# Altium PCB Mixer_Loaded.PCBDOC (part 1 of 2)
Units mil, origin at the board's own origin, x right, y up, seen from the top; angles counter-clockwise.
Board outline 16350 x 11350 mil, 2 copper layers (Top Layer, Bottom Layer); 554 components, 386 nets, 1551 pads, 0 vias.
Unrouted connection lines stored in the file: 1047.
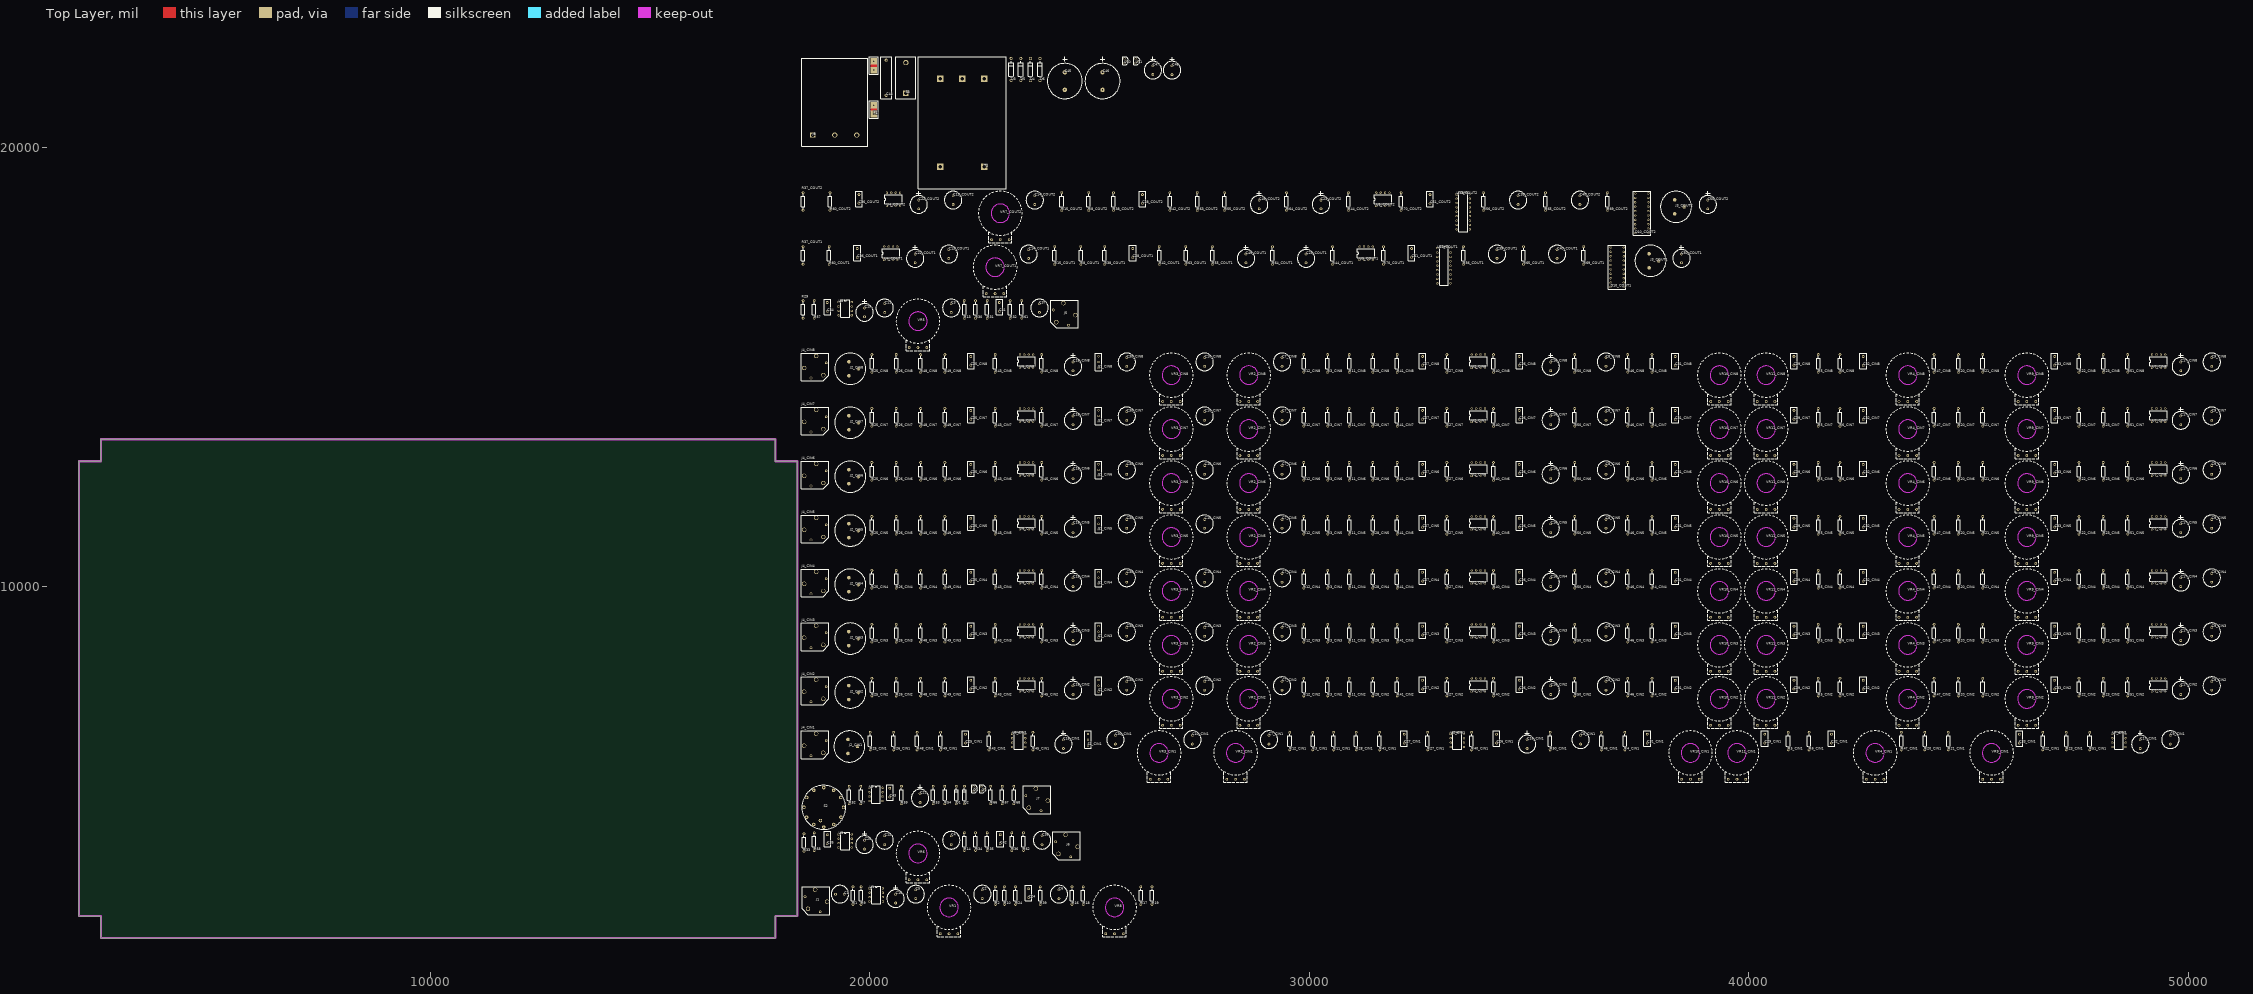
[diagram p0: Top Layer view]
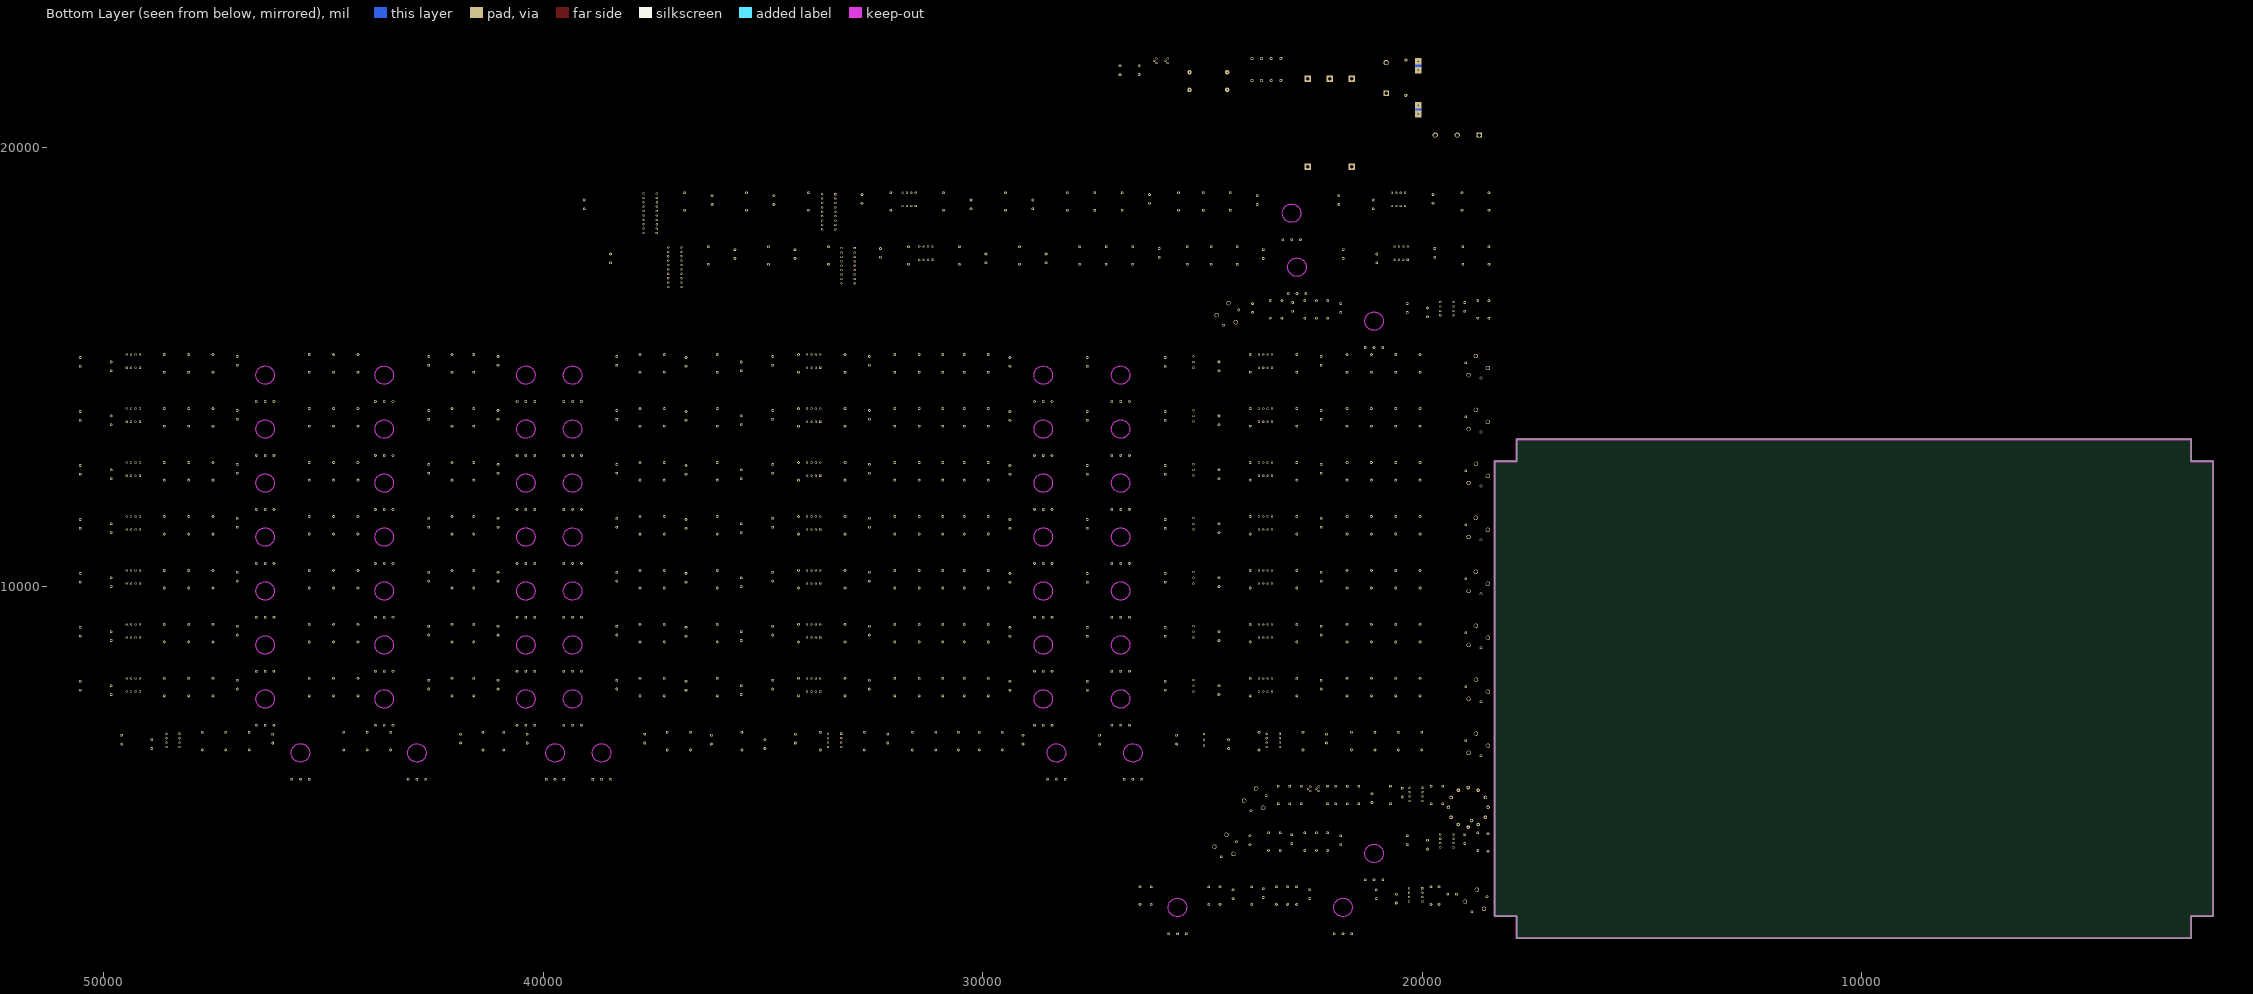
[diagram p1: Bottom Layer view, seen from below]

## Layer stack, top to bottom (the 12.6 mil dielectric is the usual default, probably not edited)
Top Layer: signal copper 1.4
Dielectric: dielectric 12.6, FR-4, Dk 4.8
Bottom Layer: signal copper 1.4

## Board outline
2500,2000 17850,2000 17850,2500 18350,2500 18350,12850 17850,12850 17850,13350 2500,13350 2500,12850 2000,12850 2000,2500 2500,2500

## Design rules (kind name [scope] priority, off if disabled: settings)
Clearance [All] p1: gap=10
FabricationTestPointUsage TestPointUsage [All] p1: valid=0 allowmultiple=FALSE
FabricationTestpoint Testpoint [All] p1: side=3 testpointundercomponent=TRUE minsize=40 maxsize=100 preferedsize=60 minholesize=0 maxholesize=40 preferedholesize=32 testpointgrid=1 allowsidetop=TRUE allowsidebottom=TRUE usegrid=TRUE gridtolerance=0.01
PolygonConnect [All] p1: connectstyle=Relief reliefconductorwidth=10 reliefentries=4 polygonreliefangle="90 Angle"
RoomDefinition Auxilary [InComponentClass('Auxilary')] p1: confinementstyle=ConfineIn formatcopy=TRUE lockcomponents=FALSE outline 18425,2025 26579.51,2025 26579.51,3203 18425,3203
RoomDefinition CIN1 [InComponentClass('CIN1')] p2: confinementstyle=ConfineIn formatcopy=TRUE lockcomponents=FALSE outline 18425,5541 49972.36,5541 49972.36,6719 18425,6719
RoomDefinition CIN2 [InComponentClass('CIN2')] p3: confinementstyle=ConfineIn formatcopy=TRUE lockcomponents=FALSE outline 18425,6769 50934.91,6769 50934.91,7947 18425,7947
RoomDefinition CIN3 [InComponentClass('CIN3')] p4: confinementstyle=ConfineIn formatcopy=TRUE lockcomponents=FALSE outline 18425,7997 50934.91,7997 50934.91,9175 18425,9175
RoomDefinition CIN4 [InComponentClass('CIN4')] p5: confinementstyle=ConfineIn formatcopy=TRUE lockcomponents=FALSE outline 18425,9225 50934.91,9225 50934.91,10403 18425,10403
RoomDefinition CIN5 [InComponentClass('CIN5')] p6: confinementstyle=ConfineIn formatcopy=TRUE lockcomponents=FALSE outline 18425,10453 50934.91,10453 50934.91,11631 18425,11631
RoomDefinition CIN6 [InComponentClass('CIN6')] p7: confinementstyle=ConfineIn formatcopy=TRUE lockcomponents=FALSE outline 18425,11681 50934.91,11681 50934.91,12859 18425,12859
RoomDefinition CIN7 [InComponentClass('CIN7')] p8: confinementstyle=ConfineIn formatcopy=TRUE lockcomponents=FALSE outline 18425,12909 50934.91,12909 50934.91,14087 18425,14087
RoomDefinition CIN8 [InComponentClass('CIN8')] p9: confinementstyle=ConfineIn formatcopy=TRUE lockcomponents=FALSE outline 18425,14137 50934.91,14137 50934.91,15315 18425,15315
RoomDefinition COUT1 [InComponentClass('COUT1')] p10: confinementstyle=ConfineIn formatcopy=TRUE lockcomponents=FALSE outline 18425,16593 38977.41,16593 38977.41,17771 18425,17771
RoomDefinition COUT2 [InComponentClass('COUT2')] p11: confinementstyle=ConfineIn formatcopy=TRUE lockcomponents=FALSE outline 18425,17821 39597.21,17821 39597.21,18999 18425,18999
RoomDefinition Effects [InComponentClass('Effects')] p12: confinementstyle=ConfineIn formatcopy=TRUE lockcomponents=FALSE outline 18425,3253 24810.54,3253 24810.54,4431 18425,4431
RoomDefinition Headphone [InComponentClass('Headphone')] p13: confinementstyle=ConfineIn formatcopy=TRUE lockcomponents=FALSE outline 18425,4450 24133.46,4450 24133.46,5491 18425,5491
RoomDefinition Monitor [InComponentClass('Monitor')] p14: confinementstyle=ConfineIn formatcopy=TRUE lockcomponents=FALSE outline 18425,15365 24750.56,15365 24750.56,16543 18425,16543
RoomDefinition Power [InComponentClass('Power')] p15: confinementstyle=ConfineIn formatcopy=TRUE lockcomponents=FALSE outline 18425,19049 27101.73,19049 27101.73,22057 18425,22057
RoutingVias [All] p1: holewidth=28 width=50 viastyle="Through Hole" minholewidth=28 minwidth=50 maxholewidth=28 maxwidth=50
SilkscreenOverComponentPads [All] p1: minsilkscreentomaskgap=10
SolderMaskExpansion [All] p1: expansion=4
Width [All] p1: maxlimit=20 minlimit=8 preferedwidth=10
25 further rules are at their usual default settings.

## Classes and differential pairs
component class Auxilary: C1 C2 C5 C6 C15 C24 J1 R1 R2 R9 R10 R16 R17 R18 R19 R24 R39 U1 VR1 VR8
component class CIN1: C7_CIN1 C8_CIN1 C9_CIN1 C10_CIN1 C16_CIN1 C17_CIN1 C18_CIN1 C25_CIN1 C26_CIN1 C27_CIN1 C29_CIN1 C30_CIN1 C31_CIN1 C32_CIN1 C33_CIN1 J2_CIN1 J4_CIN1 R3_CIN1 R4_CIN1 R5_CIN1 R6_CIN1 R11_CIN1 R12_CIN1 R20_CIN1 R21_CIN1 R22_CIN1 R23_CIN1 R25_CIN1 R26_CIN1 R27_CIN1 R28_CIN1 R40_CIN1 R41_CIN1 R43_CIN1 R45_CIN1 R46_CIN1 R47_CIN1 R48_CIN1 R49_CIN1 R50_CIN1 R51_CIN1 S1_CIN1 U2_CIN1 U6_CIN1 U7_CIN1 VR2_CIN1 VR3_CIN1 VR4_CIN1 VR9_CIN1 VR10_CIN1 VR11_CIN1
component class CIN2: C7_CIN2 C8_CIN2 C9_CIN2 C10_CIN2 C16_CIN2 C17_CIN2 C18_CIN2 C25_CIN2 C26_CIN2 C27_CIN2 C29_CIN2 C30_CIN2 C31_CIN2 C32_CIN2 C33_CIN2 J2_CIN2 J4_CIN2 R3_CIN2 R4_CIN2 R5_CIN2 R6_CIN2 R11_CIN2 R12_CIN2 R20_CIN2 R21_CIN2 R22_CIN2 R23_CIN2 R25_CIN2 R26_CIN2 R27_CIN2 R28_CIN2 R40_CIN2 R41_CIN2 R43_CIN2 R45_CIN2 R46_CIN2 R47_CIN2 R48_CIN2 R49_CIN2 R50_CIN2 R51_CIN2 S1_CIN2 U2_CIN2 U6_CIN2 U7_CIN2 VR2_CIN2 VR3_CIN2 VR4_CIN2 VR9_CIN2 VR10_CIN2 VR11_CIN2
component class CIN3: C7_CIN3 C8_CIN3 C9_CIN3 C10_CIN3 C16_CIN3 C17_CIN3 C18_CIN3 C25_CIN3 C26_CIN3 C27_CIN3 C29_CIN3 C30_CIN3 C31_CIN3 C32_CIN3 C33_CIN3 J2_CIN3 J4_CIN3 R3_CIN3 R4_CIN3 R5_CIN3 R6_CIN3 R11_CIN3 R12_CIN3 R20_CIN3 R21_CIN3 R22_CIN3 R23_CIN3 R25_CIN3 R26_CIN3 R27_CIN3 R28_CIN3 R40_CIN3 R41_CIN3 R43_CIN3 R45_CIN3 R46_CIN3 R47_CIN3 R48_CIN3 R49_CIN3 R50_CIN3 R51_CIN3 S1_CIN3 U2_CIN3 U6_CIN3 U7_CIN3 VR2_CIN3 VR3_CIN3 VR4_CIN3 VR9_CIN3 VR10_CIN3 VR11_CIN3
component class CIN4: C7_CIN4 C8_CIN4 C9_CIN4 C10_CIN4 C16_CIN4 C17_CIN4 C18_CIN4 C25_CIN4 C26_CIN4 C27_CIN4 C29_CIN4 C30_CIN4 C31_CIN4 C32_CIN4 C33_CIN4 J2_CIN4 J4_CIN4 R3_CIN4 R4_CIN4 R5_CIN4 R6_CIN4 R11_CIN4 R12_CIN4 R20_CIN4 R21_CIN4 R22_CIN4 R23_CIN4 R25_CIN4 R26_CIN4 R27_CIN4 R28_CIN4 R40_CIN4 R41_CIN4 R43_CIN4 R45_CIN4 R46_CIN4 R47_CIN4 R48_CIN4 R49_CIN4 R50_CIN4 R51_CIN4 S1_CIN4 U2_CIN4 U6_CIN4 U7_CIN4 VR2_CIN4 VR3_CIN4 VR4_CIN4 VR9_CIN4 VR10_CIN4 VR11_CIN4
component class CIN5: C7_CIN5 C8_CIN5 C9_CIN5 C10_CIN5 C16_CIN5 C17_CIN5 C18_CIN5 C25_CIN5 C26_CIN5 C27_CIN5 C29_CIN5 C30_CIN5 C31_CIN5 C32_CIN5 C33_CIN5 J2_CIN5 J4_CIN5 R3_CIN5 R4_CIN5 R5_CIN5 R6_CIN5 R11_CIN5 R12_CIN5 R20_CIN5 R21_CIN5 R22_CIN5 R23_CIN5 R25_CIN5 R26_CIN5 R27_CIN5 R28_CIN5 R40_CIN5 R41_CIN5 R43_CIN5 R45_CIN5 R46_CIN5 R47_CIN5 R48_CIN5 R49_CIN5 R50_CIN5 R51_CIN5 S1_CIN5 U2_CIN5 U6_CIN5 U7_CIN5 VR2_CIN5 VR3_CIN5 VR4_CIN5 VR9_CIN5 VR10_CIN5 VR11_CIN5
component class CIN6: C7_CIN6 C8_CIN6 C9_CIN6 C10_CIN6 C16_CIN6 C17_CIN6 C18_CIN6 C25_CIN6 C26_CIN6 C27_CIN6 C29_CIN6 C30_CIN6 C31_CIN6 C32_CIN6 C33_CIN6 J2_CIN6 J4_CIN6 R3_CIN6 R4_CIN6 R5_CIN6 R6_CIN6 R11_CIN6 R12_CIN6 R20_CIN6 R21_CIN6 R22_CIN6 R23_CIN6 R25_CIN6 R26_CIN6 R27_CIN6 R28_CIN6 R40_CIN6 R41_CIN6 R43_CIN6 R45_CIN6 R46_CIN6 R47_CIN6 R48_CIN6 R49_CIN6 R50_CIN6 R51_CIN6 S1_CIN6 U2_CIN6 U6_CIN6 U7_CIN6 VR2_CIN6 VR3_CIN6 VR4_CIN6 VR9_CIN6 VR10_CIN6 VR11_CIN6
component class CIN7: C7_CIN7 C8_CIN7 C9_CIN7 C10_CIN7 C16_CIN7 C17_CIN7 C18_CIN7 C25_CIN7 C26_CIN7 C27_CIN7 C29_CIN7 C30_CIN7 C31_CIN7 C32_CIN7 C33_CIN7 J2_CIN7 J4_CIN7 R3_CIN7 R4_CIN7 R5_CIN7 R6_CIN7 R11_CIN7 R12_CIN7 R20_CIN7 R21_CIN7 R22_CIN7 R23_CIN7 R25_CIN7 R26_CIN7 R27_CIN7 R28_CIN7 R40_CIN7 R41_CIN7 R43_CIN7 R45_CIN7 R46_CIN7 R47_CIN7 R48_CIN7 R49_CIN7 R50_CIN7 R51_CIN7 S1_CIN7 U2_CIN7 U6_CIN7 U7_CIN7 VR2_CIN7 VR3_CIN7 VR4_CIN7 VR9_CIN7 VR10_CIN7 VR11_CIN7
component class CIN8: C7_CIN8 C8_CIN8 C9_CIN8 C10_CIN8 C16_CIN8 C17_CIN8 C18_CIN8 C25_CIN8 C26_CIN8 C27_CIN8 C29_CIN8 C30_CIN8 C31_CIN8 C32_CIN8 C33_CIN8 J2_CIN8 J4_CIN8 R3_CIN8 R4_CIN8 R5_CIN8 R6_CIN8 R11_CIN8 R12_CIN8 R20_CIN8 R21_CIN8 R22_CIN8 R23_CIN8 R25_CIN8 R26_CIN8 R27_CIN8 R28_CIN8 R40_CIN8 R41_CIN8 R43_CIN8 R45_CIN8 R46_CIN8 R47_CIN8 R48_CIN8 R49_CIN8 R50_CIN8 R51_CIN8 S1_CIN8 U2_CIN8 U6_CIN8 U7_CIN8 VR2_CIN8 VR3_CIN8 VR4_CIN8 VR9_CIN8 VR10_CIN8 VR11_CIN8
component class COUT1: C13_COUT1 C14_COUT1 C22_COUT1 C23_COUT1 C28_COUT1 C36_COUT1 C39_COUT1 C40_COUT1 C49_COUT1 C50_COUT1 C51_COUT1 D10_COUT1 J3_COUT1 R8_COUT1 R15_COUT1 R37_COUT1 R38_COUT1 R42_COUT1 R44_COUT1 R55_COUT1 R56_COUT1 R60_COUT1 R63_COUT1 R64_COUT1 R65_COUT1 R69_COUT1 R70_COUT1 U4_COUT1 U5_COUT1 U12_COUT1 VR7_COUT1
component class COUT2: C13_COUT2 C14_COUT2 C22_COUT2 C23_COUT2 C28_COUT2 C36_COUT2 C39_COUT2 C40_COUT2 C49_COUT2 C50_COUT2 C51_COUT2 D10_COUT2 J3_COUT2 R8_COUT2 R15_COUT2 R37_COUT2 R38_COUT2 R42_COUT2 R44_COUT2 R55_COUT2 R56_COUT2 R60_COUT2 R63_COUT2 R64_COUT2 R65_COUT2 R69_COUT2 R70_COUT2 U4_COUT2 U5_COUT2 U12_COUT2 VR7_COUT2
component class Effects: C4 C12 C20 C35 C38 C42 J6 R14 R33 R34 R35 R36 R58 R62 U3 VR6
component class Headphone: C21 C43 D1 D2 J7 Q1 Q2 R7 R52 R53 R54 R59 R66 R67 R68 S2 U9
component class Monitor: C3 C11 C19 C34 C37 C41 J5 R13 R29 R30 R31 R32 R57 R61 U8 VR5
component class Power: C44 C45 C46 C47 C48 D3 D4 D5 D6 F1 J8 S3 T1 U10 U11
net class HEADPHONE[1..8]: HEADPHONE1 HEADPHONE2 HEADPHONE3 HEADPHONE4 HEADPHONE5 HEADPHONE6 HEADPHONE7 HEADPHONE8
net class MB[1..2]: MB1 MB2
channel class "Input channel": CIN1 CIN2 CIN3 CIN4 CIN5 CIN6 CIN7 CIN8
channel class "Output channel": COUT1 COUT2

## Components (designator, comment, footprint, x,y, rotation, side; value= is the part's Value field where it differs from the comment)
C1 "1uF" RB.2/.4-NP 19417,2999 r0 top
C2 "1uF" RB.2/.4-NP 22558.94,3099 r90 top
C3 "1uF" RB.2/.4-NP 21851.84,16439 r90 top
C4 "1uF" RB.2/.4-NP 21851.84,4327 r90 top
C5 "2.2uF" RB.2/.4-NP 21042.94,3099 r90 top
C6 "2.2uF" RB.2/.4-NP 24301.71,3099 r90 top
C7_CIN1 "2.2uF" RB.2/.4-NP 29080.47,6615 r90 top (schematic designator C7)
C7_CIN2 "2.2uF" RB.2/.4-NP 29379.38,7843 r90 top (schematic designator C7)
C7_CIN3 "2.2uF" RB.2/.4-NP 29379.38,9071 r90 top (schematic designator C7)
C7_CIN4 "2.2uF" RB.2/.4-NP 29379.38,10299 r90 top (schematic designator C7)
C7_CIN5 "2.2uF" RB.2/.4-NP 29379.38,11527 r90 top (schematic designator C7)
C7_CIN6 "2.2uF" RB.2/.4-NP 29379.38,12755 r90 top (schematic designator C7)
C7_CIN7 "2.2uF" RB.2/.4-NP 29379.38,13983 r90 top (schematic designator C7)
C7_CIN8 "2.2uF" RB.2/.4-NP 29379.38,15211 r90 top (schematic designator C7)
C8_CIN1 "2.2uF" RB.2/.4-NP 36172.73,6615 r90 top (schematic designator C8)
C8_CIN2 "2.2uF" RB.2/.4-NP 36750.56,7843 r90 top (schematic designator C8)
C8_CIN3 "2.2uF" RB.2/.4-NP 36750.56,9071 r90 top (schematic designator C8)
C8_CIN4 "2.2uF" RB.2/.4-NP 36750.56,10299 r90 top (schematic designator C8)
C8_CIN5 "2.2uF" RB.2/.4-NP 36750.56,11527 r90 top (schematic designator C8)
C8_CIN6 "2.2uF" RB.2/.4-NP 36750.56,12755 r90 top (schematic designator C8)
C8_CIN7 "2.2uF" RB.2/.4-NP 36750.56,13983 r90 top (schematic designator C8)
C8_CIN8 "2.2uF" RB.2/.4-NP 36750.56,15211 r90 top (schematic designator C8)
C9_CIN1 "2.2uF" RB.2/.4-NP 49592.48,6615 r90 top (schematic designator C9)
C9_CIN2 "2.2uF" RB.2/.4-NP 50535.03,7843 r90 top (schematic designator C9)
C9_CIN3 "2.2uF" RB.2/.4-NP 50535.03,9071 r90 top (schematic designator C9)
C9_CIN4 "2.2uF" RB.2/.4-NP 50535.03,10299 r90 top (schematic designator C9)
C9_CIN5 "2.2uF" RB.2/.4-NP 50535.03,11527 r90 top (schematic designator C9)
C9_CIN6 "2.2uF" RB.2/.4-NP 50535.03,12755 r90 top (schematic designator C9)
C9_CIN7 "2.2uF" RB.2/.4-NP 50535.03,13983 r90 top (schematic designator C9)
C9_CIN8 "2.2uF" RB.2/.4-NP 50535.03,15211 r90 top (schematic designator C9)
C10_CIN1 "2.2uF" RB.2/.4-NP 27338.6,6615 r90 top (schematic designator C10)
C10_CIN2 "2.2uF" RB.2/.4-NP 27617.52,7843 r90 top (schematic designator C10)
C10_CIN3 "2.2uF" RB.2/.4-NP 27617.52,9071 r90 top (schematic designator C10)
C10_CIN4 "2.2uF" RB.2/.4-NP 27617.52,10299 r90 top (schematic designator C10)
C10_CIN5 "2.2uF" RB.2/.4-NP 27617.52,11527 r90 top (schematic designator C10)
C10_CIN6 "2.2uF" RB.2/.4-NP 27617.52,12755 r90 top (schematic designator C10)
C10_CIN7 "2.2uF" RB.2/.4-NP 27617.52,13983 r90 top (schematic designator C10)
C10_CIN8 "2.2uF" RB.2/.4-NP 27617.52,15211 r90 top (schematic designator C10)
C11 "2.2uF" RB.2/.4-NP 20335.84,16439 r90 top
C12 "2.2uF" RB.2/.4-NP 20335.84,4327 r90 top
C13_COUT1 "2.2uF" RB.2/.4-NP 21794.21,17667 r90 top (schematic designator C13)
C13_COUT2 "2.2uF" RB.2/.4-NP 21894.18,18895 r90 top (schematic designator C13)
C14_COUT1 "2.2uF" RB.2/.4-NP 23611.89,17667 r90 top (schematic designator C14)
C14_COUT2 "2.2uF" RB.2/.4-NP 23751.85,18895 r90 top (schematic designator C14)
C15 "10uF" RB.2/.4 20584.94,2999 r90 top
C16_CIN1 "10uF" RB.2/.4 34955.01,6515 r90 top (schematic designator C16)
C16_CIN2 "10uF" RB.2/.4 35492.85,7743 r90 top (schematic designator C16)
C16_CIN3 "10uF" RB.2/.4 35492.85,8971 r90 top (schematic designator C16)
C16_CIN4 "10uF" RB.2/.4 35492.85,10199 r90 top (schematic designator C16)
C16_CIN5 "10uF" RB.2/.4 35492.85,11427 r90 top (schematic designator C16)
C16_CIN6 "10uF" RB.2/.4 35492.85,12655 r90 top (schematic designator C16)
C16_CIN7 "10uF" RB.2/.4 35492.85,13883 r90 top (schematic designator C16)
C16_CIN8 "10uF" RB.2/.4 35492.85,15111 r90 top (schematic designator C16)
C17_CIN1 "10uF" RB.2/.4 48908.61,6515 r90 top (schematic designator C17)
C17_CIN2 "10uF" RB.2/.4 49831.18,7743 r90 top (schematic designator C17)
C17_CIN3 "10uF" RB.2/.4 49831.18,8971 r90 top (schematic designator C17)
C17_CIN4 "10uF" RB.2/.4 49831.18,10199 r90 top (schematic designator C17)
C17_CIN5 "10uF" RB.2/.4 49831.18,11427 r90 top (schematic designator C17)
C17_CIN6 "10uF" RB.2/.4 49831.18,12655 r90 top (schematic designator C17)
C17_CIN7 "10uF" RB.2/.4 49831.18,13883 r90 top (schematic designator C17)
C17_CIN8 "10uF" RB.2/.4 49831.18,15111 r90 top (schematic designator C17)
C18_CIN1 "10uF" RB.2/.4 24404,6515 r90 top (schematic designator C18)
C18_CIN2 "10uF" RB.2/.4 24622.93,7743 r90 top (schematic designator C18)
C18_CIN3 "10uF" RB.2/.4 24622.93,8971 r90 top (schematic designator C18)
C18_CIN4 "10uF" RB.2/.4 24622.93,10199 r90 top (schematic designator C18)
C18_CIN5 "10uF" RB.2/.4 24622.93,11427 r90 top (schematic designator C18)
C18_CIN6 "10uF" RB.2/.4 24622.93,12655 r90 top (schematic designator C18)
C18_CIN7 "10uF" RB.2/.4 24622.93,13883 r90 top (schematic designator C18)
C18_CIN8 "10uF" RB.2/.4 24622.93,15111 r90 top (schematic designator C18)
C19 "10uF" RB.2/.4 19877.84,16339 r90 top
C20 "10uF" RB.2/.4 19877.84,4227 r90 top
C21 "10uF" RB.2/.4 21141.81,5287 r90 top
C22_COUT1 "10uF" RB.2/.4 21030.37,17567 r90 top (schematic designator C22)
C22_COUT2 "10uF" RB.2/.4 21110.35,18795 r90 top (schematic designator C22)
C23_COUT1 "10uF" RB.2/.4 29925.3,17567 r90 top (schematic designator C23)
C23_COUT2 "10uF" RB.2/.4 30265.19,18795 r90 top (schematic designator C23)
C24 "270pF" RAD0.2 23613.81,2924 r90 top
C25_CIN1 "270pF" RAD0.2 22176.53,6440 r90 top (schematic designator C25)
C25_CIN2 "270pF" RAD0.2 22296.5,7668 r90 top (schematic designator C25)
C25_CIN3 "270pF" RAD0.2 22296.5,8896 r90 top (schematic designator C25)
C25_CIN4 "270pF" RAD0.2 22296.5,10124 r90 top (schematic designator C25)
C25_CIN5 "270pF" RAD0.2 22296.5,11352 r90 top (schematic designator C25)
C25_CIN6 "270pF" RAD0.2 22296.5,12580 r90 top (schematic designator C25)
C25_CIN7 "270pF" RAD0.2 22296.5,13808 r90 top (schematic designator C25)
C25_CIN8 "270pF" RAD0.2 22296.5,15036 r90 top (schematic designator C25)
C26_CIN1 "270pF" RAD0.2 34261.15,6440 r90 top (schematic designator C26)
C26_CIN2 "270pF" RAD0.2 34778.99,7668 r90 top (schematic designator C26)
C26_CIN3 "270pF" RAD0.2 34778.99,8896 r90 top (schematic designator C26)
C26_CIN4 "270pF" RAD0.2 34778.99,10124 r90 top (schematic designator C26)
C26_CIN5 "270pF" RAD0.2 34778.99,11352 r90 top (schematic designator C26)
C26_CIN6 "270pF" RAD0.2 34778.99,12580 r90 top (schematic designator C26)
C26_CIN7 "270pF" RAD0.2 34778.99,13808 r90 top (schematic designator C26)
C26_CIN8 "270pF" RAD0.2 34778.99,15036 r90 top (schematic designator C26)
C27_CIN1 "270pF" RAD0.2 32158.69,6440 r90 top (schematic designator C27)
C27_CIN2 "270pF" RAD0.2 32577.56,7668 r90 top (schematic designator C27)
C27_CIN3 "270pF" RAD0.2 32577.56,8896 r90 top (schematic designator C27)
C27_CIN4 "270pF" RAD0.2 32577.56,10124 r90 top (schematic designator C27)
C27_CIN5 "270pF" RAD0.2 32577.56,11352 r90 top (schematic designator C27)
C27_CIN6 "270pF" RAD0.2 32577.56,12580 r90 top (schematic designator C27)
C27_CIN7 "270pF" RAD0.2 32577.56,13808 r90 top (schematic designator C27)
C27_CIN8 "270pF" RAD0.2 32577.56,15036 r90 top (schematic designator C27)
C28_COUT1 "270pF" RAD0.2 25982.27,17492 r90 top (schematic designator C28)
C28_COUT2 "270pF" RAD0.2 26202.2,18720 r90 top (schematic designator C28)
C29_CIN1 "100nF" RAD0.2 40364.22,6440 r90 top (schematic designator C29)
C29_CIN2 "100nF" RAD0.2 41027.86,7668 r90 top (schematic designator C29)
C29_CIN3 "100nF" RAD0.2 41027.86,8896 r90 top (schematic designator C29)
C29_CIN4 "100nF" RAD0.2 41027.86,10124 r90 top (schematic designator C29)
C29_CIN5 "100nF" RAD0.2 41027.86,11352 r90 top (schematic designator C29)
C29_CIN6 "100nF" RAD0.2 41027.86,12580 r90 top (schematic designator C29)
C29_CIN7 "100nF" RAD0.2 41027.86,13808 r90 top (schematic designator C29)
C29_CIN8 "100nF" RAD0.2 41027.86,15036 r90 top (schematic designator C29)
C30_CIN1 "6.8uF" RB.2/.4-NP 25586.74,6615 r90 top (schematic designator C30)
C30_CIN2 "6.8uF" RB.2/.4-NP 25845.67,7843 r90 top (schematic designator C30)
C30_CIN3 "6.8uF" RB.2/.4-NP 25845.67,9071 r90 top (schematic designator C30)
C30_CIN4 "6.8uF" RB.2/.4-NP 25845.67,10299 r90 top (schematic designator C30)
C30_CIN5 "6.8uF" RB.2/.4-NP 25845.67,11527 r90 top (schematic designator C30)
C30_CIN6 "6.8uF" RB.2/.4-NP 25845.67,12755 r90 top (schematic designator C30)
C30_CIN7 "6.8uF" RB.2/.4-NP 25845.67,13983 r90 top (schematic designator C30)
C30_CIN8 "6.8uF" RB.2/.4-NP 25845.67,15211 r90 top (schematic designator C30)
C31_CIN1 "4.7nF" RAD0.2 37689.35,6440 r90 top (schematic designator C31)
C31_CIN2 "4.7nF" RAD0.2 38327.16,7668 r90 top (schematic designator C31)
C31_CIN3 "4.7nF" RAD0.2 38327.16,8896 r90 top (schematic designator C31)
C31_CIN4 "4.7nF" RAD0.2 38327.16,10124 r90 top (schematic designator C31)
C31_CIN5 "4.7nF" RAD0.2 38327.16,11352 r90 top (schematic designator C31)
C31_CIN6 "4.7nF" RAD0.2 38327.16,12580 r90 top (schematic designator C31)
C31_CIN7 "4.7nF" RAD0.2 38327.16,13808 r90 top (schematic designator C31)
C31_CIN8 "4.7nF" RAD0.2 38327.16,15036 r90 top (schematic designator C31)
C32_CIN1 "4.7nF" RAD0.2 41880.84,6440 r90 top (schematic designator C32)
C32_CIN2 "4.7nF" RAD0.2 42604.46,7668 r90 top (schematic designator C32)
C32_CIN3 "4.7nF" RAD0.2 42604.46,8896 r90 top (schematic designator C32)
C32_CIN4 "4.7nF" RAD0.2 42604.46,10124 r90 top (schematic designator C32)
C32_CIN5 "4.7nF" RAD0.2 42604.46,11352 r90 top (schematic designator C32)
C32_CIN6 "4.7nF" RAD0.2 42604.46,12580 r90 top (schematic designator C32)
C32_CIN7 "4.7nF" RAD0.2 42604.46,13808 r90 top (schematic designator C32)
C32_CIN8 "4.7nF" RAD0.2 42604.46,15036 r90 top (schematic designator C32)
C33_CIN1 "10pF" RAD0.2 46157.29,6440 r90 top (schematic designator C33)
C33_CIN2 "10pF" RAD0.2 46960.88,7668 r90 top (schematic designator C33)
C33_CIN3 "10pF" RAD0.2 46960.88,8896 r90 top (schematic designator C33)
C33_CIN4 "10pF" RAD0.2 46960.88,10124 r90 top (schematic designator C33)
C33_CIN5 "10pF" RAD0.2 46960.88,11352 r90 top (schematic designator C33)
C33_CIN6 "10pF" RAD0.2 46960.88,12580 r90 top (schematic designator C33)
C33_CIN7 "10pF" RAD0.2 46960.88,13808 r90 top (schematic designator C33)
C33_CIN8 "10pF" RAD0.2 46960.88,15036 r90 top (schematic designator C33)
C34 "27pF" RAD0.2 19031.9,16264 r90 top
C35 "27pF" RAD0.2 19031.9,4152 r90 top
C36_COUT1 "27pF" RAD0.2 19711.68,17492 r90 top (schematic designator C36)
C36_COUT2 "27pF" RAD0.2 19751.66,18720 r90 top (schematic designator C36)
C37 "47uF" RB.2/.4-NP 23858.56,16439 r90 top
C38 "47uF" RB.2/.4-NP 23918.54,4327 r90 top
C39_COUT1 "47uF" RB.2/.4-NP 34270.19,17667 r90 top (schematic designator C39)
C39_COUT2 "47uF" RB.2/.4-NP 34750.04,18895 r90 top (schematic designator C39)
C40_COUT1 "47uF" RB.2/.4-NP 35637.87,17667 r90 top (schematic designator C40)
C40_COUT2 "47uF" RB.2/.4-NP 36157.7,18895 r90 top (schematic designator C40)
C41 "1nF" RAD0.2 22946.7,16264 r90 top
C42 "1nF" RAD0.2 22966.69,4152 r90 top
C43 "22pF" RAD0.2 20453.92,5212 r90 top
C44 "1nF / 2kV" RAD0.8 20370,21178 r90 top
C45 "1000uF" RB.4/.8 24435.82,21703 r90 top
C46 "1000uF" RB.4/.8 25293.82,21703 r90 top
C47 "10uF" RB.2/.4 26439.73,21853 r90 top
C48 "10uF" RB.2/.4 26875,21850 r90 top
C49_COUT1 "10uF" RB.2/.4 28557.62,17567 r90 top (schematic designator C49)
C49_COUT2 "10uF" RB.2/.4 28857.53,18795 r90 top (schematic designator C49)
C50_COUT1 "100uF" RB.2/.4 38467.57,17567 r90 top (schematic designator C50)
C50_COUT2 "100uF" RB.2/.4 39067.38,18795 r90 top (schematic designator C50)
C51_COUT1 "180pF" RAD0.2 32326.67,17492 r90 top (schematic designator C51)
C51_COUT2 "180pF" RAD0.2 32746.54,18720 r90 top (schematic designator C51)
D1 "1N914" DIODE0.4 21967.71,5055 r90 top
D2 "1N914" DIODE0.4 22151.68,5055 r90 top
D3 "1N4004" DIODE0.5 23214.95,21517 r90 top
D4 "1N4004" DIODE0.5 23652.88,21517 r90 top
D5 "1N4004" DIODE0.5 23433.92,21517 r90 top
D6 "1N4004" DIODE0.5 23871.85,21517 r90 top
D10_COUT1 "LED-10 BAR" "LED - 10 BAR HORIZONTAL" 36855.54,16817 r0 top (schematic designator D10)
D10_COUT2 "LED-10 BAR" "LED - 10 BAR HORIZONTAL" 37415.36,18045 r0 top (schematic designator D10)
F1 "1A" FUSE 20087,20753 r90 top
J1 "Auxilary In" JACK-6.25MM 18775,2850 r0 top
J2_CIN1 "XLR" XLR-FEMALE 19532.21,6360.67 r90 top (schematic designator J2)
J2_CIN2 "XLR" XLR-FEMALE 19552.2,7588.67 r90 top (schematic designator J2)
J2_CIN3 "XLR" XLR-FEMALE 19552.2,8816.67 r90 top (schematic designator J2)
J2_CIN4 "XLR" XLR-FEMALE 19552.2,10044.67 r90 top (schematic designator J2)
J2_CIN5 "XLR" XLR-FEMALE 19552.2,11272.67 r90 top (schematic designator J2)
J2_CIN6 "XLR" XLR-FEMALE 19552.2,12500.67 r90 top (schematic designator J2)
J2_CIN7 "XLR" XLR-FEMALE 19552.2,13728.67 r90 top (schematic designator J2)
J2_CIN8 "XLR" XLR-FEMALE 19552.2,14956.67 r90 top (schematic designator J2)
J3_COUT1 "XLR" XLR-MALE 37763.72,17412.67 r90 top (schematic designator J3)
J3_COUT2 "XLR" XLR-MALE 38343.53,18640.67 r90 top (schematic designator J3)
J4_CIN1 "STEREO JACK" JACK-6.25MM 18754,6400 r90 top (schematic designator J4)
J4_CIN2 "STEREO JACK" JACK-6.25MM 18754,7628 r90 top (schematic designator J4)
J4_CIN3 "STEREO JACK" JACK-6.25MM 18754,8856 r90 top (schematic designator J4)
J4_CIN4 "STEREO JACK" JACK-6.25MM 18754,10084 r90 top (schematic designator J4)
J4_CIN5 "STEREO JACK" JACK-6.25MM 18754,11312 r90 top (schematic designator J4)
J4_CIN6 "STEREO JACK" JACK-6.25MM 18754,12540 r90 top (schematic designator J4)
J4_CIN7 "STEREO JACK" JACK-6.25MM 18754,13768 r90 top (schematic designator J4)
J4_CIN8 "STEREO JACK" JACK-6.25MM 18754,14996 r90 top (schematic designator J4)
J5 "Monitor Send" JACK-6.25MM 24425,16200 r0 top
J6 "Effects Send" JACK-6.25MM 24475,4100 r0 top
J7 "Headphone" JACK-6.25MM 23800,5150 r0 top
J8 "CON MAINS" IEC-MAINS 18700,20275 r0 top
Q1 "BC338-25" TO-92A 22355.65,5347 r90 top
Q2 "BC328-25" TO-92A 22543.65,5347 r90 top
R1 "22k" AXIAL0.4 19615,2767 r90 top
R2 "22k" AXIAL0.4 22856.94,2767 r90 top
R3_CIN1 "22k" AXIAL0.4 30078.21,6283 r90 top (schematic designator R3)
R3_CIN2 "22k" AXIAL0.4 30417.11,7511 r90 top (schematic designator R3)
R3_CIN3 "22k" AXIAL0.4 30417.11,8739 r90 top (schematic designator R3)
R3_CIN4 "22k" AXIAL0.4 30417.11,9967 r90 top (schematic designator R3)
R3_CIN5 "22k" AXIAL0.4 30417.11,11195 r90 top (schematic designator R3)
R3_CIN6 "22k" AXIAL0.4 30417.11,12423 r90 top (schematic designator R3)
R3_CIN7 "22k" AXIAL0.4 30417.11,13651 r90 top (schematic designator R3)
R3_CIN8 "22k" AXIAL0.4 30417.11,14879 r90 top (schematic designator R3)
R4_CIN1 "22k" AXIAL0.4 37180.47,6283 r90 top (schematic designator R4)
R4_CIN2 "22k" AXIAL0.4 37798.29,7511 r90 top (schematic designator R4)
R4_CIN3 "22k" AXIAL0.4 37798.29,8739 r90 top (schematic designator R4)
R4_CIN4 "22k" AXIAL0.4 37798.29,9967 r90 top (schematic designator R4)
R4_CIN5 "22k" AXIAL0.4 37798.29,11195 r90 top (schematic designator R4)
R4_CIN6 "22k" AXIAL0.4 37798.29,12423 r90 top (schematic designator R4)
R4_CIN7 "22k" AXIAL0.4 37798.29,13651 r90 top (schematic designator R4)
R4_CIN8 "22k" AXIAL0.4 37798.29,14879 r90 top (schematic designator R4)
R5_CIN1 "22k" AXIAL0.4 40898.08,6283 r90 top (schematic designator R5)
R5_CIN2 "22k" AXIAL0.4 41581.71,7511 r90 top (schematic designator R5)
R5_CIN3 "22k" AXIAL0.4 41581.71,8739 r90 top (schematic designator R5)
R5_CIN4 "22k" AXIAL0.4 41581.71,9967 r90 top (schematic designator R5)
R5_CIN5 "22k" AXIAL0.4 41581.71,11195 r90 top (schematic designator R5)
R5_CIN6 "22k" AXIAL0.4 41581.71,12423 r90 top (schematic designator R5)
R5_CIN7 "22k" AXIAL0.4 41581.71,13651 r90 top (schematic designator R5)
R5_CIN8 "22k" AXIAL0.4 41581.71,14879 r90 top (schematic designator R5)
R6_CIN1 "22k" AXIAL0.4 41371.96,6283 r90 top (schematic designator R6)
R6_CIN2 "22k" AXIAL0.4 42075.59,7511 r90 top (schematic designator R6)
R6_CIN3 "22k" AXIAL0.4 42075.59,8739 r90 top (schematic designator R6)
R6_CIN4 "22k" AXIAL0.4 42075.59,9967 r90 top (schematic designator R6)
R6_CIN5 "22k" AXIAL0.4 42075.59,11195 r90 top (schematic designator R6)
R6_CIN6 "22k" AXIAL0.4 42075.59,12423 r90 top (schematic designator R6)
R6_CIN7 "22k" AXIAL0.4 42075.59,13651 r90 top (schematic designator R6)
R6_CIN8 "22k" AXIAL0.4 42075.59,14879 r90 top (schematic designator R6)
R7 "22k" AXIAL0.4 19792.95,5055 r90 top
R8_COUT1 "22k" AXIAL0.4 24799.57,17335 r90 top (schematic designator R8)
R8_COUT2 "22k" AXIAL0.4 24979.52,18563 r90 top (schematic designator R8)
R9 "10R" AXIAL0.4 19798.97,2767 r90 top
R10 "10R" AXIAL0.4 23060.91,2767 r90 top
R11_CIN1 "10R" AXIAL0.4 30552.09,6283 r90 top (schematic designator R11)
R11_CIN2 "10R" AXIAL0.4 30910.98,7511 r90 top (schematic designator R11)
R11_CIN3 "10R" AXIAL0.4 30910.98,8739 r90 top (schematic designator R11)
R11_CIN4 "10R" AXIAL0.4 30910.98,9967 r90 top (schematic designator R11)
R11_CIN5 "10R" AXIAL0.4 30910.98,11195 r90 top (schematic designator R11)
R11_CIN6 "10R" AXIAL0.4 30910.98,12423 r90 top (schematic designator R11)
R11_CIN7 "10R" AXIAL0.4 30910.98,13651 r90 top (schematic designator R11)
R11_CIN8 "10R" AXIAL0.4 30910.98,14879 r90 top (schematic designator R11)
R12_CIN1 "10R" AXIAL0.4 29554.35,6283 r90 top (schematic designator R12)
R12_CIN2 "10R" AXIAL0.4 29873.25,7511 r90 top (schematic designator R12)
R12_CIN3 "10R" AXIAL0.4 29873.25,8739 r90 top (schematic designator R12)
R12_CIN4 "10R" AXIAL0.4 29873.25,9967 r90 top (schematic designator R12)
R12_CIN5 "10R" AXIAL0.4 29873.25,11195 r90 top (schematic designator R12)
R12_CIN6 "10R" AXIAL0.4 29873.25,12423 r90 top (schematic designator R12)
R12_CIN7 "10R" AXIAL0.4 29873.25,13651 r90 top (schematic designator R12)
R12_CIN8 "10R" AXIAL0.4 29873.25,14879 r90 top (schematic designator R12)
R13 "10R" AXIAL0.4 22149.84,16107 r90 top
R14 "10R" AXIAL0.4 22149.84,3995 r90 top
R15_COUT1 "10R" AXIAL0.4 24205.73,17335 r90 top (schematic designator R15)
R15_COUT2 "10R" AXIAL0.4 24365.68,18563 r90 top (schematic designator R15)
R16 "15k" AXIAL0.4 24599.71,2767 r90 top
R17 "15k" AXIAL0.4 26165.61,2767 r90 top
R18 "15k" AXIAL0.4 24853.66,2767 r90 top
R19 "15k" AXIAL0.4 26419.56,2767 r90 top
R20_CIN1 "15k" AXIAL0.4 44006.56,6283 r90 top (schematic designator R20)
R20_CIN2 "15k" AXIAL0.4 44770.17,7511 r90 top (schematic designator R20)
R20_CIN3 "15k" AXIAL0.4 44770.17,8739 r90 top (schematic designator R20)
R20_CIN4 "15k" AXIAL0.4 44770.17,9967 r90 top (schematic designator R20)
R20_CIN5 "15k" AXIAL0.4 44770.17,11195 r90 top (schematic designator R20)
R20_CIN6 "15k" AXIAL0.4 44770.17,12423 r90 top (schematic designator R20)
R20_CIN7 "15k" AXIAL0.4 44770.17,13651 r90 top (schematic designator R20)
R20_CIN8 "15k" AXIAL0.4 44770.17,14879 r90 top (schematic designator R20)
R21_CIN1 "15k" AXIAL0.4 44540.42,6283 r90 top (schematic designator R21)
R21_CIN2 "15k" AXIAL0.4 45324.02,7511 r90 top (schematic designator R21)
R21_CIN3 "15k" AXIAL0.4 45324.02,8739 r90 top (schematic designator R21)
R21_CIN4 "15k" AXIAL0.4 45324.02,9967 r90 top (schematic designator R21)
R21_CIN5 "15k" AXIAL0.4 45324.02,11195 r90 top (schematic designator R21)
R21_CIN6 "15k" AXIAL0.4 45324.02,12423 r90 top (schematic designator R21)
R21_CIN7 "15k" AXIAL0.4 45324.02,13651 r90 top (schematic designator R21)
R21_CIN8 "15k" AXIAL0.4 45324.02,14879 r90 top (schematic designator R21)
R22_CIN1 "15k" AXIAL0.4 46691.15,6283 r90 top (schematic designator R22)
R22_CIN2 "15k" AXIAL0.4 47514.74,7511 r90 top (schematic designator R22)
R22_CIN3 "15k" AXIAL0.4 47514.74,8739 r90 top (schematic designator R22)
R22_CIN4 "15k" AXIAL0.4 47514.74,9967 r90 top (schematic designator R22)
R22_CIN5 "15k" AXIAL0.4 47514.74,11195 r90 top (schematic designator R22)
R22_CIN6 "15k" AXIAL0.4 47514.74,12423 r90 top (schematic designator R22)
R22_CIN7 "15k" AXIAL0.4 47514.74,13651 r90 top (schematic designator R22)
R22_CIN8 "15k" AXIAL0.4 47514.74,14879 r90 top (schematic designator R22)
R23_CIN1 "15k" AXIAL0.4 47225.01,6283 r90 top (schematic designator R23)
R23_CIN2 "15k" AXIAL0.4 48068.59,7511 r90 top (schematic designator R23)
R23_CIN3 "15k" AXIAL0.4 48068.59,8739 r90 top (schematic designator R23)
R23_CIN4 "15k" AXIAL0.4 48068.59,9967 r90 top (schematic designator R23)
R23_CIN5 "15k" AXIAL0.4 48068.59,11195 r90 top (schematic designator R23)
R23_CIN6 "15k" AXIAL0.4 48068.59,12423 r90 top (schematic designator R23)
R23_CIN7 "15k" AXIAL0.4 48068.59,13651 r90 top (schematic designator R23)
R23_CIN8 "15k" AXIAL0.4 48068.59,14879 r90 top (schematic designator R23)
R24 "2.2k" AXIAL0.4 23314.86,2767 r90 top
R25_CIN1 "2.2k" AXIAL0.4 20006.09,6283 r90 top (schematic designator R25)
R25_CIN2 "2.2k" AXIAL0.4 20046.08,7511 r90 top (schematic designator R25)
R25_CIN3 "2.2k" AXIAL0.4 20046.08,8739 r90 top (schematic designator R25)
R25_CIN4 "2.2k" AXIAL0.4 20046.08,9967 r90 top (schematic designator R25)
R25_CIN5 "2.2k" AXIAL0.4 20046.08,11195 r90 top (schematic designator R25)
R25_CIN6 "2.2k" AXIAL0.4 20046.08,12423 r90 top (schematic designator R25)
R25_CIN7 "2.2k" AXIAL0.4 20046.08,13651 r90 top (schematic designator R25)
R25_CIN8 "2.2k" AXIAL0.4 20046.08,14879 r90 top (schematic designator R25)
R26_CIN1 "2.2k" AXIAL0.4 20539.95,6283 r90 top (schematic designator R26)
R26_CIN2 "2.2k" AXIAL0.4 20599.93,7511 r90 top (schematic designator R26)
R26_CIN3 "2.2k" AXIAL0.4 20599.93,8739 r90 top (schematic designator R26)
R26_CIN4 "2.2k" AXIAL0.4 20599.93,9967 r90 top (schematic designator R26)
R26_CIN5 "2.2k" AXIAL0.4 20599.93,11195 r90 top (schematic designator R26)
R26_CIN6 "2.2k" AXIAL0.4 20599.93,12423 r90 top (schematic designator R26)
R26_CIN7 "2.2k" AXIAL0.4 20599.93,13651 r90 top (schematic designator R26)
R26_CIN8 "2.2k" AXIAL0.4 20599.93,14879 r90 top (schematic designator R26)
R27_CIN1 "2.2k" AXIAL0.4 32692.55,6283 r90 top (schematic designator R27)
R27_CIN2 "2.2k" AXIAL0.4 33131.41,7511 r90 top (schematic designator R27)
R27_CIN3 "2.2k" AXIAL0.4 33131.41,8739 r90 top (schematic designator R27)
R27_CIN4 "2.2k" AXIAL0.4 33131.41,9967 r90 top (schematic designator R27)
R27_CIN5 "2.2k" AXIAL0.4 33131.41,11195 r90 top (schematic designator R27)
R27_CIN6 "2.2k" AXIAL0.4 33131.41,12423 r90 top (schematic designator R27)
R27_CIN7 "2.2k" AXIAL0.4 33131.41,13651 r90 top (schematic designator R27)
R27_CIN8 "2.2k" AXIAL0.4 33131.41,14879 r90 top (schematic designator R27)
R28_CIN1 "2.2k" AXIAL0.4 31065.96,6283 r90 top (schematic designator R28)
R28_CIN2 "2.2k" AXIAL0.4 31444.85,7511 r90 top (schematic designator R28)
R28_CIN3 "2.2k" AXIAL0.4 31444.85,8739 r90 top (schematic designator R28)
R28_CIN4 "2.2k" AXIAL0.4 31444.85,9967 r90 top (schematic designator R28)
R28_CIN5 "2.2k" AXIAL0.4 31444.85,11195 r90 top (schematic designator R28)
R28_CIN6 "2.2k" AXIAL0.4 31444.85,12423 r90 top (schematic designator R28)
R28_CIN7 "2.2k" AXIAL0.4 31444.85,13651 r90 top (schematic designator R28)
R28_CIN8 "2.2k" AXIAL0.4 31444.85,14879 r90 top (schematic designator R28)
R29 "2.2k" AXIAL0.4 18479,16107 r90 top
R30 "2.2k" AXIAL0.4 22403.8,16107 r90 top
R31 "2.2k" AXIAL0.4 22667.74,16107 r90 top
R32 "2.2k" AXIAL0.4 23190.65,16107 r90 top
R33 "2.2k" AXIAL0.4 18500,3975 r90 top
R34 "2.2k" AXIAL0.4 22403.8,3995 r90 top
R35 "2.2k" AXIAL0.4 22667.74,3995 r90 top
R36 "2.2k" AXIAL0.4 23230.64,3995 r90 top
R37_COUT1 "2.2k" AXIAL0.4 18479,17335 r90 top (schematic designator R37)
R37_COUT2 "2.2k" AXIAL0.4 18479,18563 r90 top (schematic designator R37)
R38_COUT1 "2.2k" AXIAL0.4 25343.43,17335 r90 top (schematic designator R38)
R38_COUT2 "2.2k" AXIAL0.4 25543.37,18563 r90 top (schematic designator R38)
R39 "6.8k" AXIAL0.4 23877.76,2767 r90 top
R40_CIN1 "6.8k" AXIAL0.4 33692.29,6283 r90 top (schematic designator R40)
R40_CIN2 "6.8k" AXIAL0.4 34190.14,7511 r90 top (schematic designator R40)
R40_CIN3 "6.8k" AXIAL0.4 34190.14,8739 r90 top (schematic designator R40)
R40_CIN4 "6.8k" AXIAL0.4 34190.14,9967 r90 top (schematic designator R40)
R40_CIN5 "6.8k" AXIAL0.4 34190.14,11195 r90 top (schematic designator R40)
R40_CIN6 "6.8k" AXIAL0.4 34190.14,12423 r90 top (schematic designator R40)
R40_CIN7 "6.8k" AXIAL0.4 34190.14,13651 r90 top (schematic designator R40)
R40_CIN8 "6.8k" AXIAL0.4 34190.14,14879 r90 top (schematic designator R40)
R41_CIN1 "6.8k" AXIAL0.4 31599.82,6283 r90 top (schematic designator R41)
R41_CIN2 "6.8k" AXIAL0.4 31998.7,7511 r90 top (schematic designator R41)
R41_CIN3 "6.8k" AXIAL0.4 31998.7,8739 r90 top (schematic designator R41)
R41_CIN4 "6.8k" AXIAL0.4 31998.7,9967 r90 top (schematic designator R41)
R41_CIN5 "6.8k" AXIAL0.4 31998.7,11195 r90 top (schematic designator R41)
R41_CIN6 "6.8k" AXIAL0.4 31998.7,12423 r90 top (schematic designator R41)
R41_CIN7 "6.8k" AXIAL0.4 31998.7,13651 r90 top (schematic designator R41)
R41_CIN8 "6.8k" AXIAL0.4 31998.7,14879 r90 top (schematic designator R41)
R42_COUT1 "6.8k" AXIAL0.4 26586.11,17335 r90 top (schematic designator R42)
R42_COUT2 "6.8k" AXIAL0.4 26826.03,18563 r90 top (schematic designator R42)
R43_CIN1 "330R" AXIAL0.4 22710.4,6283 r90 top (schematic designator R43)
R43_CIN2 "330R" AXIAL0.4 22850.35,7511 r90 top (schematic designator R43)
R43_CIN3 "330R" AXIAL0.4 22850.35,8739 r90 top (schematic designator R43)
R43_CIN4 "330R" AXIAL0.4 22850.35,9967 r90 top (schematic designator R43)
R43_CIN5 "330R" AXIAL0.4 22850.35,11195 r90 top (schematic designator R43)
R43_CIN6 "330R" AXIAL0.4 22850.35,12423 r90 top (schematic designator R43)
R43_CIN7 "330R" AXIAL0.4 22850.35,13651 r90 top (schematic designator R43)
R43_CIN8 "330R" AXIAL0.4 22850.35,14879 r90 top (schematic designator R43)
R44_COUT1 "330R" AXIAL0.4 30529.14,17335 r90 top (schematic designator R44)
R44_COUT2 "330R" AXIAL0.4 30889.02,18563 r90 top (schematic designator R44)
R45_CIN1 "4.7k" AXIAL0.4 23710.14,6283 r90 top (schematic designator R45)
R45_CIN2 "4.7k" AXIAL0.4 23909.08,7511 r90 top (schematic designator R45)
R45_CIN3 "4.7k" AXIAL0.4 23909.08,8739 r90 top (schematic designator R45)
R45_CIN4 "4.7k" AXIAL0.4 23909.08,9967 r90 top (schematic designator R45)
R45_CIN5 "4.7k" AXIAL0.4 23909.08,11195 r90 top (schematic designator R45)
R45_CIN6 "4.7k" AXIAL0.4 23909.08,12423 r90 top (schematic designator R45)
R45_CIN7 "4.7k" AXIAL0.4 23909.08,13651 r90 top (schematic designator R45)
R45_CIN8 "4.7k" AXIAL0.4 23909.08,14879 r90 top (schematic designator R45)
R46_CIN1 "4.7k" AXIAL0.4 36646.61,6283 r90 top (schematic designator R46)
R46_CIN2 "4.7k" AXIAL0.4 37244.43,7511 r90 top (schematic designator R46)
R46_CIN3 "4.7k" AXIAL0.4 37244.43,8739 r90 top (schematic designator R46)
R46_CIN4 "4.7k" AXIAL0.4 37244.43,9967 r90 top (schematic designator R46)
R46_CIN5 "4.7k" AXIAL0.4 37244.43,11195 r90 top (schematic designator R46)
R46_CIN6 "4.7k" AXIAL0.4 37244.43,12423 r90 top (schematic designator R46)
R46_CIN7 "4.7k" AXIAL0.4 37244.43,13651 r90 top (schematic designator R46)
R46_CIN8 "4.7k" AXIAL0.4 37244.43,14879 r90 top (schematic designator R46)
R47_CIN1 "4.7k" AXIAL0.4 43472.7,6283 r90 top (schematic designator R47)
R47_CIN2 "4.7k" AXIAL0.4 44216.32,7511 r90 top (schematic designator R47)
R47_CIN3 "4.7k" AXIAL0.4 44216.32,8739 r90 top (schematic designator R47)
R47_CIN4 "4.7k" AXIAL0.4 44216.32,9967 r90 top (schematic designator R47)
R47_CIN5 "4.7k" AXIAL0.4 44216.32,11195 r90 top (schematic designator R47)
R47_CIN6 "4.7k" AXIAL0.4 44216.32,12423 r90 top (schematic designator R47)
R47_CIN7 "4.7k" AXIAL0.4 44216.32,13651 r90 top (schematic designator R47)
R47_CIN8 "4.7k" AXIAL0.4 44216.32,14879 r90 top (schematic designator R47)
R48_CIN1 "10k" AXIAL0.4 21073.81,6283 r90 top (schematic designator R48)
R48_CIN2 "10k" AXIAL0.4 21153.79,7511 r90 top (schematic designator R48)
R48_CIN3 "10k" AXIAL0.4 21153.79,8739 r90 top (schematic designator R48)
R48_CIN4 "10k" AXIAL0.4 21153.79,9967 r90 top (schematic designator R48)
R48_CIN5 "10k" AXIAL0.4 21153.79,11195 r90 top (schematic designator R48)
R48_CIN6 "10k" AXIAL0.4 21153.79,12423 r90 top (schematic designator R48)
R48_CIN7 "10k" AXIAL0.4 21153.79,13651 r90 top (schematic designator R48)
R48_CIN8 "10k" AXIAL0.4 21153.79,14879 r90 top (schematic designator R48)
R49_CIN1 "10k" AXIAL0.4 21607.67,6283 r90 top (schematic designator R49)
R49_CIN2 "10k" AXIAL0.4 21707.64,7511 r90 top (schematic designator R49)
R49_CIN3 "10k" AXIAL0.4 21707.64,8739 r90 top (schematic designator R49)
R49_CIN4 "10k" AXIAL0.4 21707.64,9967 r90 top (schematic designator R49)
R49_CIN5 "10k" AXIAL0.4 21707.64,11195 r90 top (schematic designator R49)
R49_CIN6 "10k" AXIAL0.4 21707.64,12423 r90 top (schematic designator R49)
R49_CIN7 "10k" AXIAL0.4 21707.64,13651 r90 top (schematic designator R49)
R49_CIN8 "10k" AXIAL0.4 21707.64,14879 r90 top (schematic designator R49)
R50_CIN1 "10k" AXIAL0.4 35478.87,6283 r90 top (schematic designator R50)
R50_CIN2 "10k" AXIAL0.4 36036.71,7511 r90 top (schematic designator R50)
R50_CIN3 "10k" AXIAL0.4 36036.71,8739 r90 top (schematic designator R50)
R50_CIN4 "10k" AXIAL0.4 36036.71,9967 r90 top (schematic designator R50)
R50_CIN5 "10k" AXIAL0.4 36036.71,11195 r90 top (schematic designator R50)
R50_CIN6 "10k" AXIAL0.4 36036.71,12423 r90 top (schematic designator R50)
R50_CIN7 "10k" AXIAL0.4 36036.71,13651 r90 top (schematic designator R50)
R50_CIN8 "10k" AXIAL0.4 36036.71,14879 r90 top (schematic designator R50)
R51_CIN1 "10k" AXIAL0.4 47758.87,6283 r90 top (schematic designator R51)
R51_CIN2 "10k" AXIAL0.4 48622.44,7511 r90 top (schematic designator R51)
R51_CIN3 "10k" AXIAL0.4 48622.44,8739 r90 top (schematic designator R51)
R51_CIN4 "10k" AXIAL0.4 48622.44,9967 r90 top (schematic designator R51)
R51_CIN5 "10k" AXIAL0.4 48622.44,11195 r90 top (schematic designator R51)
R51_CIN6 "10k" AXIAL0.4 48622.44,12423 r90 top (schematic designator R51)
R51_CIN7 "10k" AXIAL0.4 48622.44,13651 r90 top (schematic designator R51)
R51_CIN8 "10k" AXIAL0.4 48622.44,14879 r90 top (schematic designator R51)
R52 "10k" AXIAL0.4 19529,5055 r90 top
R53 "10k" AXIAL0.4 21439.81,5055 r90 top
R54 "10k" AXIAL0.4 21703.76,5055 r90 top
R55_COUT1 "10k" AXIAL0.4 27793.78,17335 r90 top (schematic designator R55)
R55_COUT2 "10k" AXIAL0.4 28073.69,18563 r90 top (schematic designator R55)
R56_COUT1 "10k" AXIAL0.4 33506.35,17335 r90 top (schematic designator R56)
R56_COUT2 "10k" AXIAL0.4 33966.21,18563 r90 top (schematic designator R56)
R57 "68k" AXIAL0.4 18732.95,16107 r90 top
R58 "68k" AXIAL0.4 18732.95,3995 r90 top
R59 "68k" AXIAL0.4 20717.86,5055 r90 top
R60_COUT1 "68k" AXIAL0.4 19072.84,17335 r90 top (schematic designator R60)
R60_COUT2 "68k" AXIAL0.4 19092.83,18563 r90 top (schematic designator R60)
R61 "100R" AXIAL0.4 23454.6,16107 r90 top
R62 "100R" AXIAL0.4 23494.59,3995 r90 top
R63_COUT1 "100R" AXIAL0.4 27189.94,17335 r90 top (schematic designator R63)
R63_COUT2 "100R" AXIAL0.4 27449.86,18563 r90 top (schematic designator R63)
R64_COUT1 "100R" AXIAL0.4 29161.46,17335 r90 top (schematic designator R64)
R64_COUT2 "100R" AXIAL0.4 29481.36,18563 r90 top (schematic designator R64)
R65_COUT1 "100R" AXIAL0.4 34874.03,17335 r90 top (schematic designator R65)
R65_COUT2 "100R" AXIAL0.4 35373.87,18563 r90 top (schematic designator R65)
R66 "33R" AXIAL0.4 22747.62,5055 r90 top
R67 "33R" AXIAL0.4 23011.57,5055 r90 top
R68 "68R" AXIAL0.4 23275.51,5055 r90 top
R69_COUT1 "270R 1W" AXIAL0.4 36241.71,17335 r90 top (schematic designator R69)
R69_COUT2 "270R 1W" AXIAL0.4 36781.53,18563 r90 top (schematic designator R69)
R70_COUT1 "680R" AXIAL0.4 31687.83,17335 r90 top (schematic designator R70)
R70_COUT2 "680R" AXIAL0.4 32087.7,18563 r90 top (schematic designator R70)
S1_CIN1 "SW SPDT" SW-SPDT 24962.86,6385 r90 top (schematic designator S1)
S1_CIN2 "SW SPDT" SW-SPDT 25201.79,7613 r90 top (schematic designator S1)
S1_CIN3 "SW SPDT" SW-SPDT 25201.79,8841 r90 top (schematic designator S1)
S1_CIN4 "SW SPDT" SW-SPDT 25201.79,10069 r90 top (schematic designator S1)
S1_CIN5 "SW SPDT" SW-SPDT 25201.79,11297 r90 top (schematic designator S1)
S1_CIN6 "SW SPDT" SW-SPDT 25201.79,12525 r90 top (schematic designator S1)
S1_CIN7 "SW SPDT" SW-SPDT 25201.79,13753 r90 top (schematic designator S1)
S1_CIN8 "SW SPDT" SW-SPDT 25201.79,14981 r90 top (schematic designator S1)
S2 "SW-12WAY" SW-12WAY 18950,4975 r0 top
S3 "Power" SW-MAINS 20818.95,21223 r90 top
T1 "30V CT" TRANSFORMER 22601.95,19553 r90 top
U1 "LM833M" DIP8 19994.94,3133.02 r0 top
U2_CIN1 "LM833M" DIP8 33218.41,6649.02 r0 top (schematic designator U2)
U2_CIN2 "LM833M" DIP8 33696.27,7611 r90 top (schematic designator U2)
U2_CIN3 "LM833M" DIP8 33696.27,8839 r90 top (schematic designator U2)
U2_CIN4 "LM833M" DIP8 33696.27,10067 r90 top (schematic designator U2)
U2_CIN5 "LM833M" DIP8 33696.27,11295 r90 top (schematic designator U2)
U2_CIN6 "LM833M" DIP8 33696.27,12523 r90 top (schematic designator U2)
U2_CIN7 "LM833M" DIP8 33696.27,13751 r90 top (schematic designator U2)
U2_CIN8 "LM833M" DIP8 33696.27,14979 r90 top (schematic designator U2)
U3 "LM833M" DIP8 19287.84,4361.02 r0 top
U4_COUT1 "LM833M" DIP8 20326.51,17435 r90 top (schematic designator U4)
U4_COUT2 "LM833M" DIP8 20386.5,18663 r90 top (schematic designator U4)
U5_COUT1 "LM833M" DIP8 31143.97,17435 r90 top (schematic designator U5)
U5_COUT2 "LM833M" DIP8 31523.85,18663 r90 top (schematic designator U5)
U6_CIN1 "SSM2017P (8)" DIP8 23236.26,6649.02 r0 top (schematic designator U6)
U6_CIN2 "SSM2017P (8)" DIP8 23415.2,7611 r90 top (schematic designator U6)
U6_CIN3 "SSM2017P (8)" DIP8 23415.2,8839 r90 top (schematic designator U6)
U6_CIN4 "SSM2017P (8)" DIP8 23415.2,10067 r90 top (schematic designator U6)
U6_CIN5 "SSM2017P (8)" DIP8 23415.2,11295 r90 top (schematic designator U6)
U6_CIN6 "SSM2017P (8)" DIP8 23415.2,12523 r90 top (schematic designator U6)
U6_CIN7 "SSM2017P (8)" DIP8 23415.2,13751 r90 top (schematic designator U6)
U6_CIN8 "SSM2017P (8)" DIP8 23415.2,14979 r90 top (schematic designator U6)
U7_CIN1 "OP27C" DIP8 48274.73,6649.02 r0 top (schematic designator U7)
U7_CIN2 "OP27C" DIP8 49177.3,7611 r90 top (schematic designator U7)
U7_CIN3 "OP27C" DIP8 49177.3,8839 r90 top (schematic designator U7)
U7_CIN4 "OP27C" DIP8 49177.3,10067 r90 top (schematic designator U7)
U7_CIN5 "OP27C" DIP8 49177.3,11295 r90 top (schematic designator U7)
U7_CIN6 "OP27C" DIP8 49177.3,12523 r90 top (schematic designator U7)
U7_CIN7 "OP27C" DIP8 49177.3,13751 r90 top (schematic designator U7)
U7_CIN8 "OP27C" DIP8 49177.3,14979 r90 top (schematic designator U7)
U8 "LM833M" DIP8 19287.84,16473.02 r0 top
U9 "TL071" DIP8 19988.92,5421.02 r0 top
U10 "78L15" TO-92A 25791.82,21913 r90 top
U11 "79L15" TO-92A 26045.77,21913 r90 top
U12_COUT1 "LM3915N(18)" DIP18 32912.51,17701.02 r0 top (schematic designator U12)
U12_COUT2 "LM3915N(18)" DIP18 33352.37,18929.02 r0 top (schematic designator U12)
VR1 "10k LOG" "POT - 24MM" 21800.94,2699 r0 top
VR2_CIN1 "10k LOG" "POT - 24MM" 28322.47,6215 r0 top (schematic designator VR2)
VR2_CIN2 "10k LOG" "POT - 24MM" 28621.38,7443 r0 top (schematic designator VR2)
VR2_CIN3 "10k LOG" "POT - 24MM" 28621.38,8671 r0 top (schematic designator VR2)
VR2_CIN4 "10k LOG" "POT - 24MM" 28621.38,9899 r0 top (schematic designator VR2)
VR2_CIN5 "10k LOG" "POT - 24MM" 28621.38,11127 r0 top (schematic designator VR2)
VR2_CIN6 "10k LOG" "POT - 24MM" 28621.38,12355 r0 top (schematic designator VR2)
VR2_CIN7 "10k LOG" "POT - 24MM" 28621.38,13583 r0 top (schematic designator VR2)
VR2_CIN8 "10k LOG" "POT - 24MM" 28621.38,14811 r0 top (schematic designator VR2)
VR3_CIN1 "10k LOG" "POT - 24MM" 26580.6,6215 r0 top (schematic designator VR3)
VR3_CIN2 "10k LOG" "POT - 24MM" 26859.52,7443 r0 top (schematic designator VR3)
VR3_CIN3 "10k LOG" "POT - 24MM" 26859.52,8671 r0 top (schematic designator VR3)
VR3_CIN4 "10k LOG" "POT - 24MM" 26859.52,9899 r0 top (schematic designator VR3)
VR3_CIN5 "10k LOG" "POT - 24MM" 26859.52,11127 r0 top (schematic designator VR3)
VR3_CIN6 "10k LOG" "POT - 24MM" 26859.52,12355 r0 top (schematic designator VR3)
VR3_CIN7 "10k LOG" "POT - 24MM" 26859.52,13583 r0 top (schematic designator VR3)
VR3_CIN8 "10k LOG" "POT - 24MM" 26859.52,14811 r0 top (schematic designator VR3)
VR4_CIN1 "10k LOG" "POT - 24MM" 42874.7,6215 r0 top (schematic designator VR4)
VR4_CIN2 "10k LOG" "POT - 24MM" 43618.32,7443 r0 top (schematic designator VR4)
VR4_CIN3 "10k LOG" "POT - 24MM" 43618.32,8671 r0 top (schematic designator VR4)
VR4_CIN4 "10k LOG" "POT - 24MM" 43618.32,9899 r0 top (schematic designator VR4)
VR4_CIN5 "10k LOG" "POT - 24MM" 43618.32,11127 r0 top (schematic designator VR4)
VR4_CIN6 "10k LOG" "POT - 24MM" 43618.32,12355 r0 top (schematic designator VR4)
VR4_CIN7 "10k LOG" "POT - 24MM" 43618.32,13583 r0 top (schematic designator VR4)
VR4_CIN8 "10k LOG" "POT - 24MM" 43618.32,14811 r0 top (schematic designator VR4)
VR5 "10k LOG" "POT - 24MM" 21093.84,16039 r0 top
VR6 "10k LOG" "POT - 24MM" 21093.84,3927 r0 top
VR7_COUT1 "10k LOG" "POT - 24MM" 22848.05,17267 r0 top (schematic designator VR7)
VR7_COUT2 "10k LOG" "POT - 24MM" 22968.01,18495 r0 top (schematic designator VR7)
VR8 "10k LIN" "POT - 24MM" 25567.61,2699 r0 top
VR9_CIN1 "10k LIN" "POT - 24MM" 45524.29,6215 r0 top (schematic designator VR9)
VR9_CIN2 "10k LIN" "POT - 24MM" 46327.88,7443 r0 top (schematic designator VR9)
VR9_CIN3 "10k LIN" "POT - 24MM" 46327.88,8671 r0 top (schematic designator VR9)
VR9_CIN4 "10k LIN" "POT - 24MM" 46327.88,9899 r0 top (schematic designator VR9)
VR9_CIN5 "10k LIN" "POT - 24MM" 46327.88,11127 r0 top (schematic designator VR9)
VR9_CIN6 "10k LIN" "POT - 24MM" 46327.88,12355 r0 top (schematic designator VR9)
VR9_CIN7 "10k LIN" "POT - 24MM" 46327.88,13583 r0 top (schematic designator VR9)
VR9_CIN8 "10k LIN" "POT - 24MM" 46327.88,14811 r0 top (schematic designator VR9)
VR10_CIN1 "100k LIN" "POT - 24MM" 38673.22,6215 r0 top (schematic designator VR10)
VR10_CIN2 "100k LIN" "POT - 24MM" 39331.02,7443 r0 top (schematic designator VR10)
VR10_CIN3 "100k LIN" "POT - 24MM" 39331.02,8671 r0 top (schematic designator VR10)
VR10_CIN4 "100k LIN" "POT - 24MM" 39331.02,9899 r0 top (schematic designator VR10)
VR10_CIN5 "100k LIN" "POT - 24MM" 39331.02,11127 r0 top (schematic designator VR10)
VR10_CIN6 "100k LIN" "POT - 24MM" 39331.02,12355 r0 top (schematic designator VR10)
VR10_CIN7 "100k LIN" "POT - 24MM" 39331.02,13583 r0 top (schematic designator VR10)
VR10_CIN8 "100k LIN" "POT - 24MM" 39331.02,14811 r0 top (schematic designator VR10)
VR11_CIN1 "20k LIN" "POT - 24MM" 39731.22,6215 r0 top (schematic designator VR11)
VR11_CIN2 "20k LIN" "POT - 24MM" 40394.86,7443 r0 top (schematic designator VR11)
VR11_CIN3 "20k LIN" "POT - 24MM" 40394.86,8671 r0 top (schematic designator VR11)
VR11_CIN4 "20k LIN" "POT - 24MM" 40394.86,9899 r0 top (schematic designator VR11)
VR11_CIN5 "20k LIN" "POT - 24MM" 40394.86,11127 r0 top (schematic designator VR11)
VR11_CIN6 "20k LIN" "POT - 24MM" 40394.86,12355 r0 top (schematic designator VR11)
VR11_CIN7 "20k LIN" "POT - 24MM" 40394.86,13583 r0 top (schematic designator VR11)
VR11_CIN8 "20k LIN" "POT - 24MM" 40394.86,14811 r0 top (schematic designator VR11)

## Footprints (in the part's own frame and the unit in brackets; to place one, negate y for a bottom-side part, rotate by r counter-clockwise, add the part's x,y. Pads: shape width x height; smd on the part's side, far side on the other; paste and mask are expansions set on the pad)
AXIAL0.4 [mil]
  round 62 hole 32: 1(0,0) 2(400,0)
  silkscreen extent 40,-40 360,40
DIODE0.4 [mil]
  round 62 hole 32: 1(0,0) 2(400,0)
  silkscreen extent 40,-40 360,40
DIODE0.5 [mil]
  round 70 hole 40: 1(0,0) 2(500,0)
  silkscreen extent 60,-55 440,55
DIP8 [mil]
  rect 50x50 hole 32: 1(0,0)
  round 50 hole 32: 2(0,-100) 3(0,-200) 4(0,-300) 5(300,-300) 6(300,-200) 7(300,-100) 8(300,0)
  silkscreen extent 50,-350 250,50
DIP18 [mil]
  rect 50x50 hole 32: 1(0,0)
  round 50 hole 32: 2(0,-100) 3(0,-200) 4(0,-300) 5(0,-400) 6(0,-500) 7(0,-600) 8(0,-700) 9(0,-800) 10(300,-800) 11(300,-700) 12(300,-600) 13(300,-500) 14(300,-400) 15(300,-300) 16(300,-200) 17(300,-100) 18(300,0)
  silkscreen extent 50,-850 250,50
